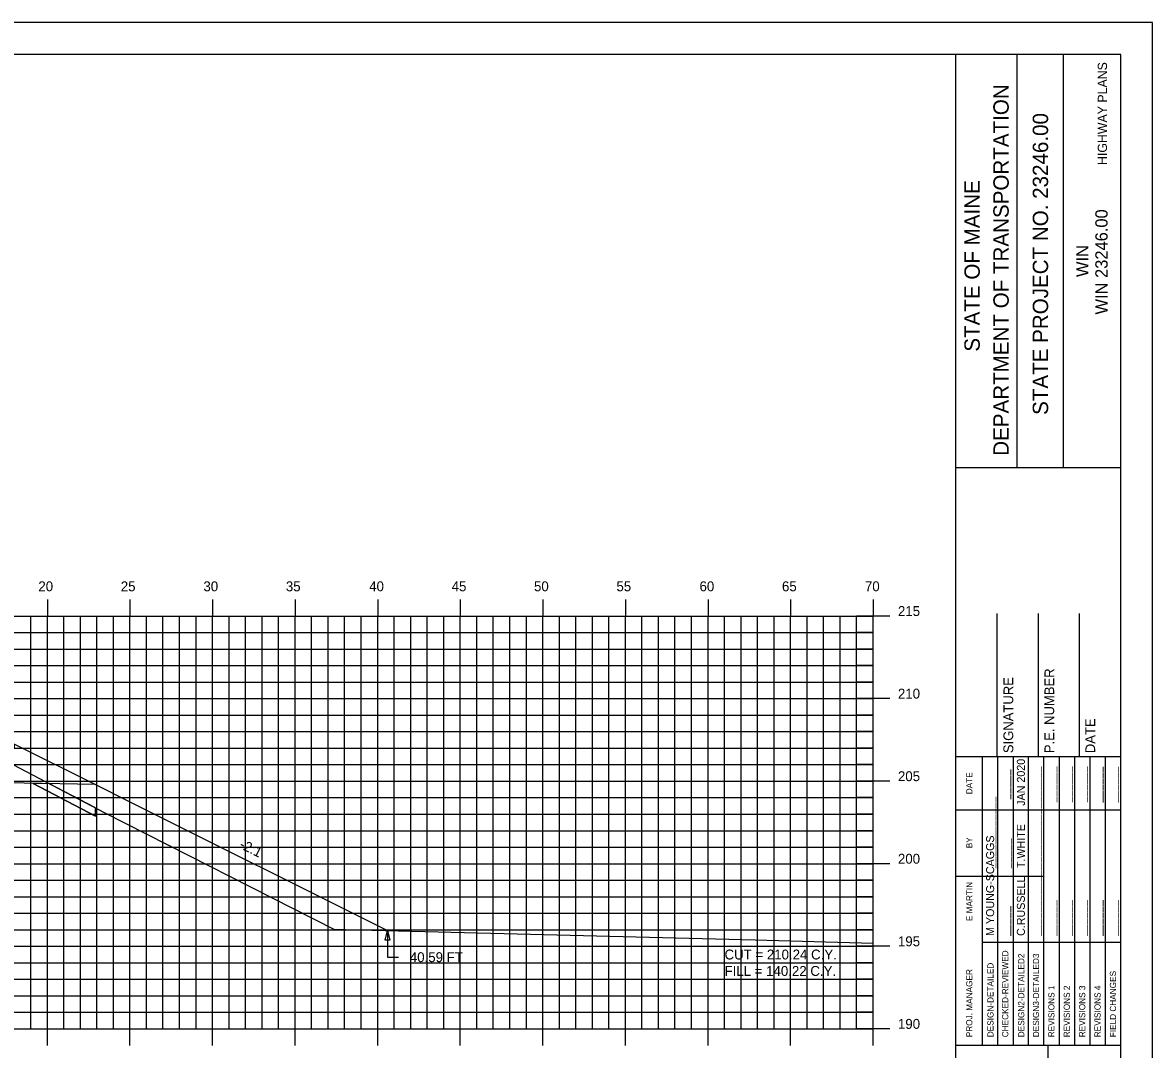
# Model space of a CAD drawing. Extents: x 1138541 to 1138711, y 608981 to 609091.
# Drawn here: x 1138642.9 to 1138711.3, y 609029.1 to 609091.3 of the extents above; entities that cross this region are included whole.
import ezdxf

# ---------------------------------------------------------------- set-up
doc = ezdxf.new("R2010")
doc.units = 0
for name, color, linetype in [('ANNOTATION', 7, 'Continuous'), ('BORDER', 7, 'Continuous'), ('D_Roadway_SlopeLines', 7, 'Continuous'), ('D_Roadway_SubGrade', 7, 'Continuous'), ('D_Text_Standard', 7, 'Continuous'), ('H_V ANNOTATION', 7, 'Continuous'), ('HIGHWAY_TITLE', 7, 'Continuous'), ('MAJOR', 7, 'Continuous'), ('MINOR', 7, 'Continuous'), ('PLOT BOUNDARY', 7, 'Continuous'), ('S_Roadway_Centerline', 7, 'Continuous'), ('SHADING', 7, 'Continuous')]:
    doc.layers.add(name, color=color, linetype=linetype)

msp = doc.modelspace()

# ---------------------------------------------------------------- linework, layer by layer
msp.add_lwpolyline([(1138571.881, 609035.544), (1138596.379, 609044.08), (1138599.249, 609045.08), (1138606.435, 609047.584), (1138606.436, 609047.584), (1138613.436, 609047.864), (1138624.436, 609048.084), (1138635.436, 609047.864), (1138642.436, 609047.584), (1138647.352, 609045.125), (1138649.352, 609044.125), (1138665.029, 609036.287)])
at = {"layer": 'BORDER'}
for p, q in [((1138699.436, 608984.335), (1138699.436, 609089.335)), ((1138703.164, 609064.332), (1138703.164, 609089.332)), ((1138705.959, 609064.332), (1138705.959, 609089.332)), ((1138699.437, 609064.329), (1138709.436, 609064.329)), ((1138701.936, 609046.838), (1138701.936, 609055.485)), ((1138704.436, 609046.838), (1138704.436, 609055.485)), ((1138706.936, 609046.838), (1138706.936, 609055.485)), ((1138699.436, 609046.838), (1138709.436, 609046.838)), ((1138699.436, 609029.338), (1138709.436, 609029.338)), ((1138705.027, 608994.338), (1138705.027, 609029.338))]:
    msp.add_line(p, q, dxfattribs=at)
msp.add_lwpolyline([(1138549.436, 608984.335), (1138709.436, 608984.335), (1138709.436, 609089.335), (1138549.436, 609089.335)], close=True, dxfattribs=at)
for points in [[(1138701.051, 609043.588), (1138701.051, 609046.838)], [(1138701.983, 609029.341), (1138701.983, 609046.838)], [(1138702.915, 609046.838), (1138702.915, 609029.341)], [(1138703.847, 609029.341), (1138703.847, 609046.838)], [(1138704.778, 609029.341), (1138704.778, 609046.838)], [(1138705.71, 609029.341), (1138705.71, 609046.838)], [(1138706.642, 609029.341), (1138706.642, 609046.838)], [(1138707.573, 609029.341), (1138707.573, 609046.838)], [(1138708.505, 609029.341), (1138708.505, 609046.838)], [(1138701.052, 609029.341), (1138701.052, 609046.132)], [(1138699.436, 609043.588), (1138709.436, 609043.588)], [(1138699.436, 609039.588), (1138701.052, 609039.588)], [(1138701.051, 609039.588), (1138704.777, 609039.588)], [(1138701.051, 609035.588), (1138709.436, 609035.588)]]:
    msp.add_lwpolyline(points, dxfattribs=at)
at = {"layer": 'D_Roadway_SlopeLines'}
for points in [[(1138647.352, 609043.716), (1138647.352, 609043.216), (1138643.576, 609045.201)], [(1138647.352, 609045.125), (1138649.352, 609044.125)], [(1138649.352, 609044.125), (1138665.029, 609036.287)]]:
    msp.add_lwpolyline(points, dxfattribs=at)
at = {"layer": 'D_Roadway_SubGrade'}
msp.add_lwpolyline([(1138635.436, 609047.447), (1138635.436, 609047.614), (1138642.436, 609047.334), (1138642.436, 609047.584), (1138642.436, 609047.584), (1138647.352, 609045.125), (1138635.436, 609045.364)], close=True, dxfattribs=at)
at = {"layer": 'D_Text_Standard'}
msp.add_lwpolyline([(1138665.029, 609036.287), (1138665.173, 609035.704), (1138664.881, 609035.705)], close=True, dxfattribs=at)
msp.add_lwpolyline([(1138665.029, 609036.287), (1138665.023, 609034.675), (1138665.703, 609034.675)], dxfattribs=at)
at = {"layer": 'MAJOR'}
for p, q in [((1138644.436, 609056.337), (1138644.436, 609055.335)), ((1138649.436, 609056.337), (1138649.436, 609055.335)), ((1138654.436, 609056.337), (1138654.436, 609055.335)), ((1138659.436, 609056.337), (1138659.436, 609055.335)), ((1138664.436, 609056.337), (1138664.436, 609055.335)), ((1138669.436, 609056.337), (1138669.436, 609055.335)), ((1138674.436, 609056.337), (1138674.436, 609055.335)), ((1138679.436, 609056.337), (1138679.436, 609055.335)), ((1138684.436, 609056.337), (1138684.436, 609055.335)), ((1138689.436, 609056.337), (1138689.436, 609055.335)), ((1138694.436, 609056.337), (1138694.436, 609055.335)), ((1138554.436, 609055.335), (1138694.436, 609055.335)), ((1138554.436, 609055.335), (1138694.436, 609055.335)), ((1138644.436, 609030.335), (1138644.436, 609055.335)), ((1138649.436, 609030.335), (1138649.436, 609055.335)), ((1138654.436, 609030.335), (1138654.436, 609055.335)), ((1138659.436, 609030.335), (1138659.436, 609055.335)), ((1138664.436, 609030.335), (1138664.436, 609055.335)), ((1138669.436, 609030.335), (1138669.436, 609055.335)), ((1138674.436, 609030.335), (1138674.436, 609055.335)), ((1138679.436, 609030.335), (1138679.436, 609055.335)), ((1138684.436, 609030.335), (1138684.436, 609055.335)), ((1138689.436, 609030.335), (1138689.436, 609055.335)), ((1138695.438, 609055.335), (1138693.434, 609055.335)), ((1138694.436, 609030.335), (1138694.436, 609055.335)), ((1138694.436, 609030.335), (1138694.436, 609055.335)), ((1138554.436, 609050.335), (1138694.436, 609050.335)), ((1138695.438, 609050.335), (1138693.434, 609050.335)), ((1138554.436, 609045.335), (1138694.436, 609045.335)), ((1138695.438, 609045.335), (1138693.434, 609045.335)), ((1138554.436, 609040.335), (1138694.436, 609040.335)), ((1138695.438, 609040.335), (1138693.434, 609040.335)), ((1138554.436, 609035.335), (1138694.436, 609035.335)), ((1138695.438, 609035.335), (1138693.434, 609035.335)), ((1138554.436, 609030.335), (1138694.436, 609030.335)), ((1138554.436, 609030.335), (1138694.436, 609030.335)), ((1138644.436, 609029.333), (1138644.436, 609030.335)), ((1138649.436, 609029.333), (1138649.436, 609030.335)), ((1138654.436, 609029.333), (1138654.436, 609030.335)), ((1138659.436, 609029.333), (1138659.436, 609030.335)), ((1138664.436, 609029.333), (1138664.436, 609030.335)), ((1138669.436, 609029.333), (1138669.436, 609030.335)), ((1138674.436, 609029.333), (1138674.436, 609030.335)), ((1138679.436, 609029.333), (1138679.436, 609030.335)), ((1138684.436, 609029.333), (1138684.436, 609030.335)), ((1138689.436, 609029.333), (1138689.436, 609030.335)), ((1138695.438, 609030.335), (1138693.434, 609030.335)), ((1138694.436, 609029.333), (1138694.436, 609030.335))]:
    msp.add_line(p, q, dxfattribs=at)
at = {"layer": 'MINOR'}
for p, q in [((1138643.436, 609030.335), (1138643.436, 609055.335)), ((1138645.436, 609030.335), (1138645.436, 609055.335)), ((1138646.436, 609030.335), (1138646.436, 609055.335)), ((1138647.436, 609030.335), (1138647.436, 609055.335)), ((1138648.436, 609030.335), (1138648.436, 609055.335)), ((1138650.436, 609030.335), (1138650.436, 609055.335)), ((1138651.436, 609030.335), (1138651.436, 609055.335)), ((1138652.436, 609030.335), (1138652.436, 609055.335)), ((1138653.436, 609030.335), (1138653.436, 609055.335)), ((1138655.436, 609030.335), (1138655.436, 609055.335)), ((1138656.436, 609030.335), (1138656.436, 609055.335)), ((1138657.436, 609030.335), (1138657.436, 609055.335)), ((1138658.436, 609030.335), (1138658.436, 609055.335)), ((1138660.436, 609030.335), (1138660.436, 609055.335)), ((1138661.436, 609030.335), (1138661.436, 609055.335)), ((1138662.436, 609030.335), (1138662.436, 609055.335)), ((1138663.436, 609030.335), (1138663.436, 609055.335)), ((1138665.436, 609030.335), (1138665.436, 609055.335)), ((1138666.436, 609030.335), (1138666.436, 609055.335)), ((1138667.436, 609030.335), (1138667.436, 609055.335)), ((1138668.436, 609030.335), (1138668.436, 609055.335)), ((1138670.436, 609030.335), (1138670.436, 609055.335)), ((1138671.436, 609030.335), (1138671.436, 609055.335)), ((1138672.436, 609030.335), (1138672.436, 609055.335)), ((1138673.436, 609030.335), (1138673.436, 609055.335)), ((1138675.436, 609030.335), (1138675.436, 609055.335)), ((1138676.436, 609030.335), (1138676.436, 609055.335)), ((1138677.436, 609030.335), (1138677.436, 609055.335)), ((1138678.436, 609030.335), (1138678.436, 609055.335)), ((1138680.436, 609030.335), (1138680.436, 609055.335)), ((1138681.436, 609030.335), (1138681.436, 609055.335)), ((1138682.436, 609030.335), (1138682.436, 609055.335)), ((1138683.436, 609030.335), (1138683.436, 609055.335)), ((1138685.436, 609030.335), (1138685.436, 609055.335)), ((1138686.436, 609030.335), (1138686.436, 609055.335)), ((1138687.436, 609030.335), (1138687.436, 609055.335)), ((1138688.436, 609030.335), (1138688.436, 609055.335)), ((1138690.436, 609030.335), (1138690.436, 609055.335)), ((1138691.436, 609030.335), (1138691.436, 609055.335)), ((1138692.436, 609030.335), (1138692.436, 609055.335)), ((1138693.436, 609030.335), (1138693.436, 609055.335)), ((1138554.436, 609054.335), (1138694.436, 609054.335)), ((1138694.436, 609054.335), (1138693.434, 609054.335)), ((1138554.436, 609053.335), (1138694.436, 609053.335)), ((1138694.436, 609053.335), (1138693.434, 609053.335)), ((1138554.436, 609052.335), (1138694.436, 609052.335)), ((1138694.436, 609052.335), (1138693.434, 609052.335)), ((1138554.436, 609051.335), (1138694.436, 609051.335)), ((1138694.436, 609051.335), (1138693.434, 609051.335)), ((1138554.436, 609049.335), (1138694.436, 609049.335)), ((1138694.436, 609049.335), (1138693.434, 609049.335)), ((1138554.436, 609048.335), (1138694.436, 609048.335)), ((1138694.436, 609048.335), (1138693.434, 609048.335)), ((1138554.436, 609047.335), (1138694.436, 609047.335)), ((1138694.436, 609047.335), (1138693.434, 609047.335)), ((1138554.436, 609046.335), (1138694.436, 609046.335)), ((1138694.436, 609046.335), (1138693.434, 609046.335)), ((1138554.436, 609044.335), (1138694.436, 609044.335)), ((1138694.436, 609044.335), (1138693.434, 609044.335)), ((1138554.436, 609043.335), (1138694.436, 609043.335)), ((1138694.436, 609043.335), (1138693.434, 609043.335)), ((1138554.436, 609042.335), (1138694.436, 609042.335)), ((1138694.436, 609042.335), (1138693.434, 609042.335)), ((1138554.436, 609041.335), (1138694.436, 609041.335)), ((1138694.436, 609041.335), (1138693.434, 609041.335)), ((1138554.436, 609039.335), (1138694.436, 609039.335)), ((1138694.436, 609039.335), (1138693.434, 609039.335)), ((1138554.436, 609038.335), (1138694.436, 609038.335)), ((1138694.436, 609038.335), (1138693.434, 609038.335)), ((1138554.436, 609037.335), (1138694.436, 609037.335)), ((1138694.436, 609037.335), (1138693.434, 609037.335)), ((1138554.436, 609036.335), (1138694.436, 609036.335)), ((1138694.436, 609036.335), (1138693.434, 609036.335)), ((1138554.436, 609034.335), (1138694.436, 609034.335)), ((1138694.436, 609034.335), (1138693.434, 609034.335)), ((1138554.436, 609033.335), (1138694.436, 609033.335)), ((1138694.436, 609033.335), (1138693.434, 609033.335)), ((1138554.436, 609032.335), (1138694.436, 609032.335)), ((1138694.436, 609032.335), (1138693.434, 609032.335)), ((1138554.436, 609031.335), (1138694.436, 609031.335)), ((1138694.436, 609031.335), (1138693.434, 609031.335))]:
    msp.add_line(p, q, dxfattribs=at)
at = {"layer": 'PLOT BOUNDARY'}
msp.add_lwpolyline([(1138541.342, 608981.276), (1138711.342, 608981.276), (1138711.342, 609091.276), (1138541.342, 609091.276)], close=True, dxfattribs=at)
at = {"layer": 'S_Roadway_Centerline'}
msp.add_lwpolyline([(1138554.436, 609035.937), (1138564.348, 609035.608), (1138576.51, 609035.505), (1138582.147, 609035.513), (1138595.011, 609041.436), (1138600.099, 609043.642), (1138601.178, 609044.211), (1138603.452, 609045.123), (1138609.46, 609047.658), (1138613.125, 609048.519), (1138613.787, 609048.68), (1138622.737, 609048.805), (1138624.066, 609048.82), (1138633.517, 609048.617), (1138634.998, 609048.588), (1138635.372, 609048.523), (1138638.378, 609048.433), (1138647.922, 609043.417), (1138661.813, 609036.36), (1138662.484, 609036.351), (1138687.297, 609035.724), (1138694.436, 609035.519)], dxfattribs=at)
at = {"layer": 'SHADING'}
for p, q in [((1138644.565, 609045.181), (1138643.576, 609045.201)), ((1138647.352, 609043.716), (1138644.565, 609045.181))]:
    msp.add_line(p, q, dxfattribs=at)
msp.add_lwpolyline([(1138643.576, 609045.201), (1138647.352, 609043.216), (1138647.352, 609043.716)], dxfattribs=at)

# ---------------------------------------------------------------- texts
at = {"layer": 'ANNOTATION'}
msp.add_text('-2:1', height=0.6, rotation=333.43495, dxfattribs=at).set_placement((1138656.014, 609041.312))
at = {"layer": 'BORDER'}
for s, height, p in [('DEPARTMENT OF TRANSPORTATION', 0.93176, (1138702.643, 609065.041)), ('STATE PROJECT NO. 23246.00', 0.93176, (1138705.028, 609067.517)), ('STATE OF MAINE', 0.93176, (1138700.891, 609071.347)), ('WIN 23246.00', 0.74527, (1138708.631, 609073.596)), ('WIN', 0.7453, (1138707.473, 609075.865)), ('SIGNATURE', 0.5906, (1138702.916, 609047.03)), ('P.E. NUMBER', 0.59055, (1138705.397, 609047.03)), ('DATE', 0.5906, (1138707.877, 609047.03)), ('JAN 2020', 0.4845, (1138703.622, 609043.843)), ('______', 0.4845, (1138704.517, 609044.063)), ('______', 0.4845, (1138705.448, 609044.065)), ('______', 0.4845, (1138706.38, 609044.067)), ('______', 0.4845, (1138707.312, 609044.067)), ('______', 0.4845, (1138708.243, 609044.036)), ('______', 0.4845, (1138709.175, 609044.036)), ('DATE', 0.3714, (1138700.44, 609044.544)), ('_____', 0.4845, (1138702.653, 609044.243)), ('____________', 0.48455, (1138701.759, 609040.073)), ('____________', 0.48455, (1138704.517, 609040.073)), ('T.WHITE', 0.4845, (1138703.622, 609040.073)), ('M YOUNG-SCAGGS', 0.48455, (1138701.759, 609035.961)), ('BY', 0.3714, (1138700.44, 609041.273)), ('_____', 0.4845, (1138702.69, 609040.073)), ('____________', 0.48455, (1138704.517, 609035.961)), ('C.RUSSELL', 0.4845, (1138703.622, 609035.961)), ('E MARTIN', 0.3727, (1138700.44, 609036.855)), ('______', 0.4845, (1138705.448, 609035.961)), ('______', 0.4845, (1138706.38, 609035.961)), ('______', 0.4845, (1138707.312, 609035.961)), ('______', 0.4845, (1138708.243, 609035.961)), ('______', 0.4845, (1138709.175, 609035.961)), ('_____', 0.4845, (1138702.653, 609035.961)), ('CHECKED-REVIEWED', 0.37275, (1138702.617, 609029.826)), ('DESIGN2-DETAILED2', 0.37275, (1138703.586, 609029.826)), ('DESIGN3-DETAILED3', 0.37275, (1138704.48, 609029.826)), ('PROJ. MANAGER', 0.37275, (1138700.44, 609029.826)), ('DESIGN-DETAILED', 0.37275, (1138701.722, 609029.826)), ('FIELD CHANGES', 0.37275, (1138709.139, 609029.826)), ('REVISIONS 1', 0.37275, (1138705.412, 609029.826)), ('REVISIONS 2', 0.37275, (1138706.344, 609029.826)), ('REVISIONS 3', 0.37275, (1138707.275, 609029.826)), ('REVISIONS 4', 0.37275, (1138708.207, 609029.826))]:
    msp.add_text(s, height=height, rotation=90, dxfattribs=at).set_placement(p)
at = {"layer": 'D_Text_Standard'}
for s, p in [('CUT = 210.24 C.Y.', (1138685.436, 609034.535)), ('40.59 FT', (1138666.383, 609034.375)), ('FILL = 140.22 C.Y.', (1138685.436, 609033.539))]:
    msp.add_text(s, height=0.6, dxfattribs=at).set_placement(p)
at = {"layer": 'H_V ANNOTATION'}
for s, p in [('20', (1138643.89, 609056.835)), ('25', (1138648.882, 609056.835)), ('30', (1138653.884, 609056.835)), ('35', (1138658.876, 609056.835)), ('40', (1138663.922, 609056.835)), ('45', (1138668.914, 609056.835)), ('50', (1138673.9, 609056.835)), ('55', (1138678.892, 609056.835)), ('60', (1138683.922, 609056.835)), ('65', (1138688.914, 609056.835)), ('70', (1138693.938, 609056.835)), ('215', (1138695.936, 609055.335)), ('210', (1138695.936, 609050.335)), ('205', (1138695.936, 609045.335)), ('200', (1138695.936, 609040.335)), ('195', (1138695.936, 609035.335)), ('190', (1138695.936, 609030.335))]:
    msp.add_text(s, height=0.6, dxfattribs=at).set_placement(p)
at = {"layer": 'HIGHWAY_TITLE'}
msp.add_text('HIGHWAY PLANS', height=0.55901, rotation=90, dxfattribs=at).set_placement((1138708.594, 609082.65))

doc.saveas('drawing.dxf')
